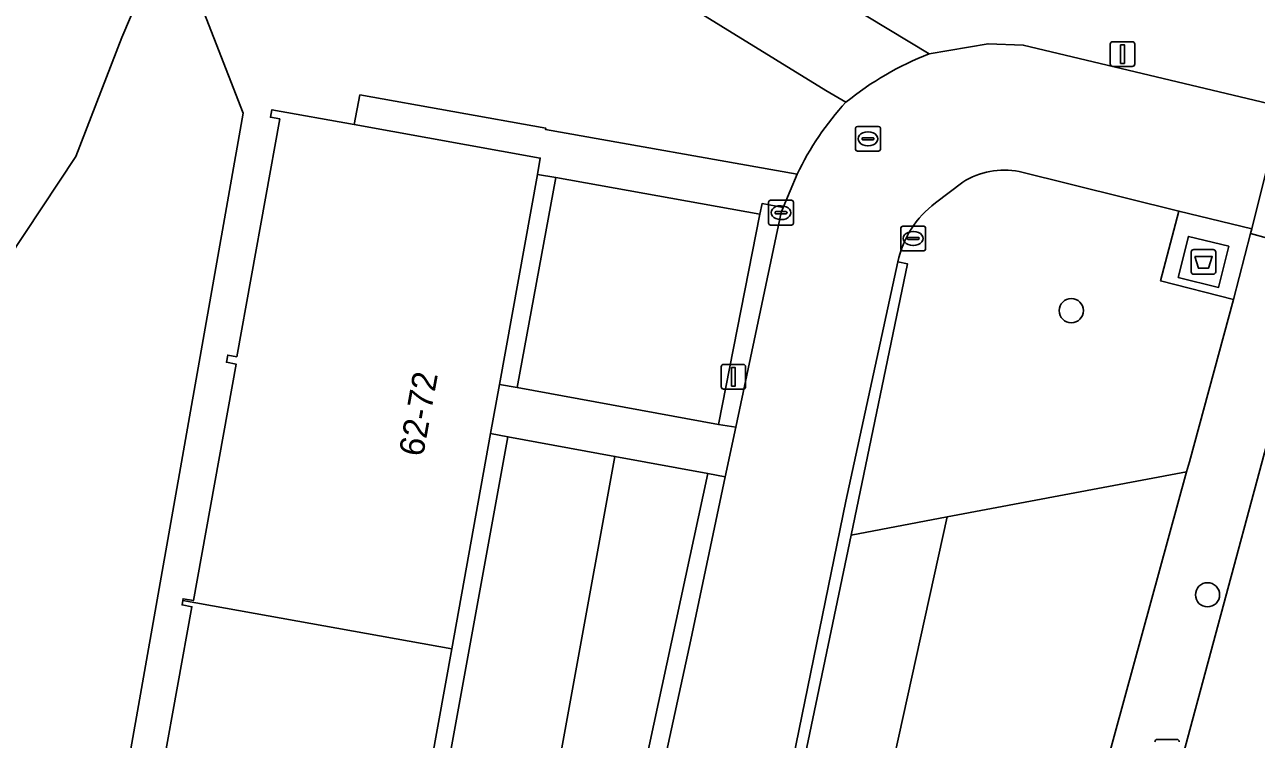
# Model space of a CAD drawing. Extents: x 161402 to 161933, y 381647 to 382315.
# Drawn here: x 161719.49 to 161769.31, y 381767.41 to 381796.34 of the extents above; entities that cross this region are included whole.
import ezdxf

# ---------------------------------------------------------------- set-up
doc = ezdxf.new("R2010")
doc.units = 0
for name, color, linetype in [('IMGEO_Afval_apart_plaats', 7, 'Continuous'), ('IMGEO_Boom', 7, 'Continuous'), ('IMGEO_Groenvoorziening', 7, 'Continuous'), ('IMGEO_Haag', 7, 'Continuous'), ('IMGEO_Kolk', 7, 'Continuous'), ('IMGEO_Lichtmast', 7, 'Continuous'), ('IMGEO_Pand', 7, 'Continuous'), ('IMGEO_Pand_nummerreeks', 7, 'Continuous'), ('IMGEO_Rijbaan_lokaal_open', 7, 'Continuous'), ('IMGEO_Rioolput', 7, 'Continuous'), ('IMGEO_Voetpad_gesloten', 7, 'Continuous'), ('IMGEO_Voetpad_halfverhard', 7, 'Continuous'), ('IMGEO_Voetpad_open', 7, 'Continuous')]:
    doc.layers.add(name, color=color, linetype=linetype)

msp = doc.modelspace()

# ---------------------------------------------------------------- linework, layer by layer
at = {"layer": 'IMGEO_Afval_apart_plaats'}
for p, q in [((161766.678, 381786.338), (161766.678, 381787.138)), ((161766.678, 381787.138), (161766.678, 381786.338)), ((161766.778, 381787.238), (161767.568, 381787.238)), ((161767.568, 381787.238), (161766.778, 381787.238)), ((161767.668, 381787.138), (161767.668, 381786.338)), ((161767.668, 381786.338), (161767.668, 381787.138)), ((161767.568, 381786.238), (161766.778, 381786.238)), ((161766.778, 381786.238), (161767.568, 381786.238))]:
    msp.add_line(p, q, dxfattribs=at)
msp.add_lwpolyline([(161766.821, 381786.952), (161767.525, 381786.952), (161767.376, 381786.482), (161766.97, 381786.482), (161766.821, 381786.952)], dxfattribs=at)
for centre, start, end in [((161766.778, 381787.138), 90, 180), ((161766.778, 381787.138), 90, 180), ((161767.568, 381787.138), 0, 90), ((161767.568, 381787.138), 360, 90), ((161766.778, 381786.338), 180, 270), ((161766.778, 381786.338), 180, 270), ((161767.568, 381786.338), 270, 0), ((161767.568, 381786.338), 270, 0)]:
    msp.add_arc(centre, 0.1, start, end, dxfattribs=at)
at = {"layer": 'IMGEO_Boom'}
for centre in [(161761.826, 381784.763), (161767.337, 381773.264)]:
    msp.add_circle(centre, 0.489, dxfattribs=at)
at = {"layer": 'IMGEO_Groenvoorziening'}
for points in [[(161751.227, 381807.036), (161751.647, 381809.088), (161748.122, 381809.717), (161744.303, 381807.358), (161730.467, 381815.628), (161730.018, 381810.901), (161756.079, 381795.155), (161758.458, 381795.562), (161759.883, 381795.508), (161770.352, 381793.016), (161772.812, 381803.355)], [(161702.956, 381716.799), (161715.379, 381719.409), (161720.782, 381750), (161728.333, 381792.761), (161725.367, 381800.387), (161723.418, 381795.819), (161721.564, 381791.006), (161718.107, 381785.811), (161715.357, 381771.588), (161712.581, 381759.611), (161705.894, 381734.943), (161702.23, 381724.444)], [(161749.235, 381788.673), (161740.973, 381790.147), (161739.418, 381781.648), (161747.559, 381780.155)], [(161752.919, 381775.683), (161755.207, 381786.658), (161754.814, 381786.734), (161752.712, 381777.049), (161748.925, 381758.53), (161749.327, 381758.447)], [(161743.366, 381778.862), (161739.042, 381779.66), (161735.779, 381761.706), (161740.106, 381760.913)], [(161747.124, 381778.168), (161743.366, 381778.862), (161740.106, 381760.913), (161743.283, 381760.33)], [(161760.494, 381756.959), (161763.257, 381766.412), (161766.489, 381778.241), (161756.802, 381776.413), (161752.695, 381757.755), (161752.861, 381757.721), (161752.71, 381756.957), (161752.527, 381756.994), (161750.987, 381750), (161745.247, 381723.935), (161749.043, 381720.61), (161752.356, 381730.461), (161755.4, 381740.142), (161756.942, 381745.046), (161758.254, 381749.595)], [(161756.802, 381776.413), (161752.919, 381775.683), (161749.327, 381758.447), (161752.695, 381757.755)]]:
    msp.add_lwpolyline(points, close=True, dxfattribs=at)
for points in [[(161752.712, 381793.202), (161751.894, 381793.676), (161728.625, 381808.023), (161725.367, 381800.387), (161728.333, 381792.761), (161720.782, 381750), (161715.379, 381719.409), (161702.956, 381716.799), (161700.216, 381716.223), (161699.316, 381716.034), (161697.703, 381711.335), (161731.537, 381712.814), (161733.72, 381713.227)], [(161718.107, 381785.811), (161721.564, 381791.006), (161723.418, 381795.819), (161725.367, 381800.387), (161723.882, 381804.205), (161720.531, 381803.314), (161719.883, 381803.471), (161719.659, 381804.119), (161719.659, 381806.175), (161720.944, 381807.67), (161716.413, 381806.426)], [(161724.523, 381763.142), (161726.26, 381772.781), (161725.859, 381772.854), (161725.892, 381773.039), (161725.904, 381773.107), (161726.319, 381773.033), (161728.044, 381782.603), (161727.652, 381782.673), (161727.705, 381782.966), (161728.075, 381782.9), (161729.809, 381792.524), (161729.437, 381792.591), (161729.493, 381792.897), (161732.824, 381792.297), (161733.055, 381793.494), (161740.57, 381792.155), (161740.559, 381792.096), (161750.739, 381790.282)], [(161757.437, 381789.963), (161756.328, 381789.121)], [(161768.393, 381785.21), (161765.44, 381785.967), (161766.182, 381788.795), (161759.721, 381790.398)], [(161754.814, 381786.734), (161755.207, 381786.658), (161752.919, 381775.683), (161756.802, 381776.413), (161766.489, 381778.241), (161766.601, 381778.65), (161768.393, 381785.21)]]:
    msp.add_lwpolyline(points, dxfattribs=at)
for centre, radius, start, end in [((161761.407, 381785.2), 11.817, 137.3783, 154.5291), ((161759.137, 381787.251), 3.201, 79.4869, 122.0794), ((161758.71, 381785.937), 3.977, 126.7952, 168.4334)]:
    msp.add_arc(centre, radius, start, end, dxfattribs=at)
at = {"layer": 'IMGEO_Haag'}
msp.add_lwpolyline([(161755.207, 381786.658), (161754.814, 381786.734), (161752.712, 381777.049), (161748.925, 381758.53), (161749.327, 381758.447), (161752.919, 381775.683)], close=True, dxfattribs=at)
at = {"layer": 'IMGEO_Kolk'}
for p, q in [((161749.585, 381788.303), (161749.585, 381789.155)), ((161749.66, 381789.229), (161750.512, 381789.229)), ((161750.073, 381789.009), (161750.098, 381789.009)), ((161750.586, 381789.155), (161750.586, 381788.303)), ((161749.844, 381788.723), (161749.844, 381788.735)), ((161750.282, 381788.686), (161749.884, 381788.686)), ((161749.887, 381788.772), (161750.285, 381788.772)), ((161750.096, 381788.449), (161750.071, 381788.449)), ((161750.328, 381788.735), (161750.328, 381788.723)), ((161750.512, 381788.229), (161749.66, 381788.229)), ((161754.933, 381787.258), (161754.933, 381788.11)), ((161755.008, 381788.184), (161755.86, 381788.184)), ((161755.421, 381787.964), (161755.446, 381787.964)), ((161755.934, 381788.11), (161755.934, 381787.258)), ((161755.192, 381787.678), (161755.192, 381787.69)), ((161755.63, 381787.641), (161755.232, 381787.641)), ((161755.235, 381787.727), (161755.633, 381787.727)), ((161755.676, 381787.69), (161755.676, 381787.678)), ((161755.86, 381787.184), (161755.008, 381787.184)), ((161755.444, 381787.404), (161755.419, 381787.404))]:
    msp.add_line(p, q, dxfattribs=at)
for points in [[(161749.585, 381788.303), (161749.585, 381789.155)], [(161749.66, 381789.229), (161750.512, 381789.229)], [(161750.586, 381789.155), (161750.586, 381788.303)], [(161750.512, 381788.229), (161749.66, 381788.229)], [(161754.933, 381787.258), (161754.933, 381788.11)], [(161755.008, 381788.184), (161755.86, 381788.184)], [(161755.934, 381788.11), (161755.934, 381787.258)], [(161755.86, 381787.184), (161755.008, 381787.184)]]:
    msp.add_lwpolyline(points, dxfattribs=at)
for centre, radius, start, end in [((161749.662, 381789.153), 0.0765, 91.552, 178.448), ((161749.662, 381789.153), 0.0765, 91.552, 178.448), ((161750.51, 381789.153), 0.0765, 1.552, 88.448), ((161750.51, 381789.153), 0.0765, 1.552, 88.448), ((161749.884, 381788.732), 0.0403, 85.8775, 175.7526), ((161749.881, 381788.722), 0.0366, 178.938, 274.7102), ((161750.285, 381788.729), 0.043, 264.8664, 352.4533), ((161750.289, 381788.734), 0.0386, 1.7309, 96.639), ((161749.662, 381788.305), 0.0765, 181.552, 268.448), ((161749.662, 381788.305), 0.0765, 181.552, 268.448), ((161750.51, 381788.305), 0.0765, 271.552, 358.448), ((161750.51, 381788.305), 0.0765, 271.552, 358.448), ((161755.01, 381788.108), 0.0765, 91.552, 178.448), ((161755.01, 381788.108), 0.0765, 91.552, 178.448), ((161755.858, 381788.108), 0.0765, 1.552, 88.448), ((161755.858, 381788.108), 0.0765, 1.552, 88.448), ((161755.232, 381787.687), 0.0403, 85.8775, 175.7526), ((161755.229, 381787.677), 0.0366, 178.938, 274.7102), ((161755.633, 381787.684), 0.043, 264.8664, 352.4533), ((161755.637, 381787.689), 0.0386, 1.7309, 96.639), ((161755.01, 381787.26), 0.0765, 181.552, 268.448), ((161755.01, 381787.26), 0.0765, 181.552, 268.448), ((161755.858, 381787.26), 0.0765, 271.552, 358.448), ((161755.858, 381787.26), 0.0765, 271.552, 358.448)]:
    msp.add_arc(centre, radius, start, end, dxfattribs=at)
for centre, major_axis, ratio, start_param, end_param in [((161750.072, 381788.729), (-0.387, 0.002), 0.722429, 4.712389, 7.853982), ((161750.097, 381788.729), (-0.39, 0.002), 0.717154, 1.570796, 4.712389), ((161755.42, 381787.684), (-0.387, 0.002), 0.722429, 4.712389, 7.853982), ((161755.445, 381787.684), (-0.39, 0.002), 0.717154, 1.570796, 4.712389)]:
    msp.add_ellipse(centre, major_axis=major_axis, ratio=ratio, start_param=start_param, end_param=end_param, dxfattribs=at)
at = {"layer": 'IMGEO_Lichtmast'}
for p, q in [((161763.403, 381794.747), (161763.403, 381795.547)), ((161763.403, 381795.547), (161763.403, 381794.747)), ((161763.503, 381795.647), (161764.293, 381795.647)), ((161764.293, 381795.647), (161763.503, 381795.647)), ((161764.393, 381795.547), (161764.393, 381794.747)), ((161764.393, 381794.747), (161764.393, 381795.547)), ((161764.293, 381794.647), (161763.503, 381794.647)), ((161763.503, 381794.647), (161764.293, 381794.647)), ((161747.666, 381781.686), (161747.666, 381782.486)), ((161747.666, 381782.486), (161747.666, 381781.686)), ((161747.766, 381782.586), (161748.556, 381782.586)), ((161748.556, 381782.586), (161747.766, 381782.586)), ((161748.656, 381782.486), (161748.656, 381781.686)), ((161748.656, 381781.686), (161748.656, 381782.486)), ((161748.556, 381781.586), (161747.766, 381781.586)), ((161747.766, 381781.586), (161748.556, 381781.586)), ((161765.306, 381767.413), (161766.096, 381767.413)), ((161766.096, 381767.413), (161765.306, 381767.413))]:
    msp.add_line(p, q, dxfattribs=at)
for points in [[(161763.823, 381795.522), (161763.973, 381795.522), (161763.973, 381794.772), (161763.823, 381794.772), (161763.823, 381795.522)], [(161748.086, 381782.461), (161748.236, 381782.461), (161748.236, 381781.711), (161748.086, 381781.711), (161748.086, 381782.461)]]:
    msp.add_lwpolyline(points, dxfattribs=at)
for centre, start, end in [((161763.503, 381795.547), 90, 180), ((161763.503, 381795.547), 90, 180), ((161764.293, 381795.547), 0, 90), ((161764.293, 381795.547), 360, 90), ((161763.503, 381794.747), 180, 270), ((161763.503, 381794.747), 180, 270), ((161764.293, 381794.747), 270, 0), ((161764.293, 381794.747), 270, 0), ((161747.766, 381782.486), 90, 180), ((161747.766, 381782.486), 90, 180), ((161748.556, 381782.486), 0, 90), ((161748.556, 381782.486), 360, 90), ((161747.766, 381781.686), 180, 270), ((161747.766, 381781.686), 180, 270), ((161748.556, 381781.686), 270, 0), ((161748.556, 381781.686), 270, 0), ((161765.306, 381767.313), 90, 180), ((161765.306, 381767.313), 90, 180), ((161766.096, 381767.313), 0, 90), ((161766.096, 381767.313), 360, 90)]:
    msp.add_arc(centre, 0.1, start, end, dxfattribs=at)
at = {"layer": 'IMGEO_Pand'}
for points in [[(161740.232, 381790.279), (161740.351, 381790.941), (161732.824, 381792.297), (161729.493, 381792.897), (161729.437, 381792.591), (161729.809, 381792.524), (161728.075, 381782.9), (161727.705, 381782.966), (161727.652, 381782.673), (161728.044, 381782.603), (161726.319, 381773.033), (161725.904, 381773.107), (161725.892, 381773.039), (161736.771, 381771.078), (161738.341, 381779.789), (161738.7, 381781.78)], [(161736.771, 381771.078), (161725.892, 381773.039), (161725.859, 381772.854), (161726.26, 381772.781), (161724.523, 381763.142), (161724.114, 381763.215), (161724.064, 381762.939), (161724.443, 381762.871), (161722.724, 381753.337), (161722.338, 381753.407), (161722.297, 381753.177), (161733.19, 381751.213), (161734.783, 381760.053), (161735.104, 381761.83)]]:
    msp.add_lwpolyline(points, close=True, dxfattribs=at)
at = {"layer": 'IMGEO_Rijbaan_lokaal_open'}
for points in [[(161759.721, 381790.398), (161766.182, 381788.795), (161769.129, 381788.074), (161770.352, 381793.016), (161759.883, 381795.508), (161758.458, 381795.562), (161756.079, 381795.155)], [(161750.739, 381790.282), (161750.171, 381788.934), (161750.086, 381788.733), (161749.053, 381783.805), (161748.256, 381780.047), (161747.829, 381778.032), (161746.433, 381771.446), (161743.993, 381760.2), (161743.602, 381758.386), (161741.798, 381750), (161740.649, 381744.661), (161739.789, 381740.808), (161739.363, 381738.9), (161738.423, 381734.691), (161737.326, 381729.802), (161736.974, 381728.265), (161736.105, 381723.922)], [(161756.328, 381789.121), (161757.437, 381789.963)], [(161740.88, 381721.689), (161741.956, 381726.652), (161747.061, 381750), (161748.698, 381757.489), (161748.758, 381757.763), (161748.925, 381758.53), (161752.712, 381777.049), (161754.814, 381786.734)], [(161773.885, 381763.815), (161774.891, 381767.424), (161775.635, 381770.131), (161776.112, 381771.915), (161776.586, 381773.699), (161777.931, 381778.837), (161770.158, 381780.913), (161765.505, 381763.644), (161761.5, 381750), (161761.259, 381749.201), (161758.985, 381741.778)]]:
    msp.add_lwpolyline(points, dxfattribs=at)
for centre, radius, start, end in [((161760.66, 381783.378), 12.637, 111.2562, 128.9749), ((161761.407, 381785.2), 11.817, 137.3783, 154.5291), ((161759.137, 381787.251), 3.201, 79.4869, 122.0794), ((161758.71, 381785.937), 3.977, 126.7952, 168.4334)]:
    msp.add_arc(centre, radius, start, end, dxfattribs=at)
at = {"layer": 'IMGEO_Rioolput'}
for p, q in [((161753.103, 381791.292), (161753.103, 381792.144)), ((161753.178, 381792.218), (161754.03, 381792.218)), ((161753.591, 381791.998), (161753.616, 381791.998)), ((161754.104, 381792.144), (161754.104, 381791.292)), ((161753.362, 381791.712), (161753.362, 381791.724)), ((161753.8, 381791.675), (161753.402, 381791.675)), ((161753.405, 381791.761), (161753.803, 381791.761)), ((161753.614, 381791.438), (161753.589, 381791.438)), ((161753.846, 381791.724), (161753.846, 381791.712)), ((161754.03, 381791.218), (161753.178, 381791.218))]:
    msp.add_line(p, q, dxfattribs=at)
for points in [[(161753.103, 381791.292), (161753.103, 381792.144)], [(161753.178, 381792.218), (161754.03, 381792.218)], [(161754.104, 381792.144), (161754.104, 381791.292)], [(161754.03, 381791.218), (161753.178, 381791.218)]]:
    msp.add_lwpolyline(points, dxfattribs=at)
for centre, radius, start, end in [((161753.18, 381792.142), 0.0765, 91.552, 178.448), ((161753.18, 381792.142), 0.0765, 91.552, 178.448), ((161754.028, 381792.142), 0.0765, 1.552, 88.448), ((161754.028, 381792.142), 0.0765, 1.552, 88.448), ((161753.402, 381791.721), 0.0403, 85.8775, 175.7526), ((161753.399, 381791.711), 0.0366, 178.938, 274.7102), ((161753.803, 381791.718), 0.043, 264.8664, 352.4533), ((161753.807, 381791.723), 0.0386, 1.7309, 96.639), ((161753.18, 381791.294), 0.0765, 181.552, 268.448), ((161753.18, 381791.294), 0.0765, 181.552, 268.448), ((161754.028, 381791.294), 0.0765, 271.552, 358.448), ((161754.028, 381791.294), 0.0765, 271.552, 358.448)]:
    msp.add_arc(centre, radius, start, end, dxfattribs=at)
for centre, major_axis, ratio, start_param, end_param in [((161753.59, 381791.718), (-0.387, 0.002), 0.722429, 4.712389, 7.853982), ((161753.615, 381791.718), (-0.39, 0.002), 0.717154, 1.570796, 4.712389)]:
    msp.add_ellipse(centre, major_axis=major_axis, ratio=ratio, start_param=start_param, end_param=end_param, dxfattribs=at)
at = {"layer": 'IMGEO_Voetpad_gesloten'}
for points in [[(161730.018, 381810.901), (161728.625, 381808.023), (161751.894, 381793.676), (161752.712, 381793.202)], [(161756.079, 381795.155), (161730.018, 381810.901)]]:
    msp.add_lwpolyline(points, dxfattribs=at)
msp.add_lwpolyline([(161768.195, 381787.368), (161766.562, 381787.771), (161766.152, 381786.108), (161767.785, 381785.705)], close=True, dxfattribs=at)
msp.add_arc((161760.66, 381783.378), 12.637, 111.2562, 128.9749, dxfattribs=at)
at = {"layer": 'IMGEO_Voetpad_halfverhard'}
for points in [[(161740.973, 381790.147), (161740.232, 381790.279), (161738.7, 381781.78), (161739.418, 381781.648)], [(161739.042, 381779.66), (161738.341, 381779.789), (161736.771, 381771.078), (161735.104, 381761.83), (161735.779, 381761.706)]]:
    msp.add_lwpolyline(points, close=True, dxfattribs=at)
at = {"layer": 'IMGEO_Voetpad_open'}
for points in [[(161733.055, 381793.494), (161732.824, 381792.297), (161740.351, 381790.941), (161740.232, 381790.279), (161740.973, 381790.147), (161749.235, 381788.673), (161749.323, 381789.094), (161750.171, 381788.934), (161750.739, 381790.282), (161740.559, 381792.096), (161740.57, 381792.155)], [(161773.151, 381792.659), (161772.163, 381792.892), (161772.094, 381792.597), (161770.352, 381793.016), (161769.129, 381788.074), (161769.079, 381787.881), (161769.757, 381787.691), (161769.689, 381787.431), (161770.729, 381787.152), (161770.657, 381786.865), (161771.65, 381786.618)], [(161750.086, 381788.733), (161750.171, 381788.934), (161749.323, 381789.094), (161749.235, 381788.673), (161747.559, 381780.155), (161748.256, 381780.047), (161749.053, 381783.805)], [(161769.079, 381787.881), (161769.129, 381788.074), (161766.182, 381788.795), (161765.44, 381785.967), (161768.393, 381785.21)], [(161767.785, 381785.705), (161766.152, 381786.108), (161766.562, 381787.771), (161768.195, 381787.368)], [(161748.256, 381780.047), (161747.559, 381780.155), (161739.418, 381781.648), (161738.7, 381781.78), (161738.341, 381779.789), (161739.042, 381779.66), (161743.366, 381778.862), (161747.124, 381778.168), (161747.829, 381778.032)], [(161746.433, 381771.446), (161747.829, 381778.032), (161747.124, 381778.168), (161743.283, 381760.33), (161743.993, 381760.2)]]:
    msp.add_lwpolyline(points, close=True, dxfattribs=at)
msp.add_lwpolyline([(161761.259, 381749.201), (161761.5, 381750), (161765.505, 381763.644), (161770.158, 381780.913), (161770.862, 381783.591), (161771.65, 381786.618), (161770.657, 381786.865), (161770.729, 381787.152), (161769.689, 381787.431), (161769.757, 381787.691), (161769.079, 381787.881), (161768.393, 381785.21), (161766.601, 381778.65), (161766.489, 381778.241), (161763.257, 381766.412), (161760.494, 381756.959), (161758.254, 381749.595), (161756.942, 381745.046), (161755.4, 381740.142), (161752.356, 381730.461), (161749.043, 381720.61), (161745.877, 381711.196)], dxfattribs=at)

# ---------------------------------------------------------------- texts
at = {"layer": 'IMGEO_Pand_nummerreeks'}
msp.add_text('62-72', height=1, rotation=79.7844, dxfattribs=at).set_placement((161735.605, 381778.82))

doc.saveas('drawing.dxf')
